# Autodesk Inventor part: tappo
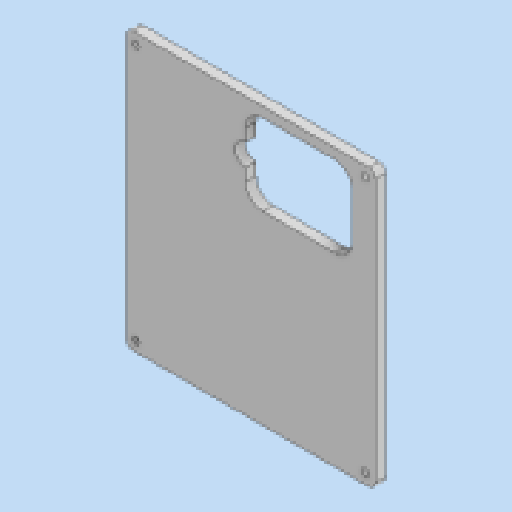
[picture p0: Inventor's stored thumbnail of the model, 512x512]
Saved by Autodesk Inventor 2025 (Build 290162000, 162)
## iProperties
Created: 2025-03
Part Number: tappo
Material: Generico
Document SubType Name: Modeling
Designer: Ryzen5700u
Density: 1 g/cm^3
Appearance: Default
Author: Ryzen5700u
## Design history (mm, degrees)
sketch "Schizzo1"
  geometry: L1 (-13.5, -12.599)-(15.5, -12.599) reference; L2 (15.5, -12.599)-(15.5, -10.099) reference; L3 (15.5, -10.099)-(-7, -10.099) reference; L4 (-7, -10.099)-(-13, -5.599) reference; L5 (-13, -5.599)-(-13, 60.901) reference; L6 (-13, 60.901)-(-7, 66.901) reference; L7 (-7, 66.901)-(50, 66.901) reference; L8 (50, 66.901)-(56, 62.401) reference; L9 (56, 62.401)-(56, -5.432) reference; L10 (56, -5.432)-(52.5, -10.099) reference; L11 (52.5, -10.099)-(52.5, -12.599) reference; L12 (52.5, -12.599)-(56.5, -12.599) reference; L13 (58.5, -10.599)-(58.5, 67.401) reference; L14 (56.5, 69.401)-(-13.5, 69.401) reference; L15 (-15.5, 67.401)-(-15.5, -10.599) reference; L16 (52.5, -12.599)-(15.5, -12.599); L17 (51.5, 47.401)-(51.5, 61.401) reference; L18 (46.5, 66.401)-(25, 66.401) reference; L19 (25, 42.401)-(46.5, 42.401) reference; L20 (20, 61.401)-(20, 47.401) reference; C1 r 1 at (-12.5, 66.401) reference; C2 r 1 at (55.5, 66.401) reference; C3 r 1 at (55.5, -9.599) reference; C4 r 1 at (-12.5, -9.599) reference; C5 r 3.23 at (20, 54.401); A1 r 2 centre (-13.5, -10.599) between (-15.5, -10.599) and (-13.5, -12.599) reference; A2 r 2 centre (56.5, -10.599) between (56.5, -12.599) and (58.5, -10.599) reference; A3 r 2 centre (56.5, 67.401) between (58.5, 67.401) and (56.5, 69.401) reference; A4 r 2 centre (-13.5, 67.401) between (-13.5, 69.401) and (-15.5, 67.401) reference; A5 r 5 centre (46.5, 61.401) between (51.5, 61.401) and (46.5, 66.401) reference; A6 r 5 centre (46.5, 47.401) between (46.5, 42.401) and (51.5, 47.401) reference; A7 r 5 centre (25, 47.401) between (20, 47.401) and (25, 42.401) reference; A8 r 5 centre (25, 61.401) between (25, 66.401) and (20, 61.401) reference; 3 further points
  constraints: 2 end point, 1 centre point, 1 horizontal, 1 midpoint
extrude "Estrusione1" new body sketch "Schizzo1" distance "d0" = 3; taper "d1" = 0 deg
sketch "Schizzo2"
  geometry: L1 (58.5, -10.599)-(58.5, 67.401) reference; L2 (56.5, 69.401)-(-13.5, 69.401) reference; L3 (-15.5, 67.401)-(-15.5, -10.599) reference; L4 (-13.5, -12.599)-(56.5, -12.599) reference; L5 (25, 66.401)-(46.5, 66.401) reference; L6 (51.5, 61.401)-(51.5, 47.401) reference; L7 (46.5, 42.401)-(25, 42.401) reference; L8 (20, 47.401)-(20, 51.171) reference; L9 (20, 57.631)-(20, 61.401) reference; L10 (50.5, 47.401)-(50.5, 61.401); L11 (46.5, 65.401)-(25, 65.401); L12 (21, 61.401)-(21, 56.395); L13 (21, 52.408)-(21, 47.401); L14 (25, 43.401)-(46.5, 43.401); C1 r 1 at (-12.5, -9.599) reference; C2 r 1 at (55.5, -9.599) reference; C3 r 1 at (55.5, 66.401) reference; C4 r 1 at (-12.5, 66.401) reference; A1 r 2 centre (56.5, -10.599) between (56.5, -12.599) and (58.5, -10.599) reference; A2 r 2 centre (56.5, 67.401) between (58.5, 67.401) and (56.5, 69.401) reference; A3 r 2 centre (-13.5, 67.401) between (-13.5, 69.401) and (-15.5, 67.401) reference; A4 r 2 centre (-13.5, -10.599) between (-15.5, -10.599) and (-13.5, -12.599) reference; A5 r 5 centre (25, 61.401) between (25, 66.401) and (20, 61.401) reference; A6 r 5 centre (46.5, 61.401) between (51.5, 61.401) and (46.5, 66.401) reference; A7 r 5 centre (46.5, 47.401) between (46.5, 42.401) and (51.5, 47.401) reference; A8 r 5 centre (25, 47.401) between (20, 47.401) and (25, 42.401) reference; A9 r 3.23 centre (20, 54.401) between (20, 57.631) and (20, 51.171) reference; A10 r 4 centre (46.5, 61.401) between (50.5, 61.401) and (46.5, 65.401); A11 r 4 centre (25, 61.401) between (25, 65.401) and (21, 61.401); A12 r 2.23 centre (20, 54.401) between (21, 56.395) and (21, 52.408); A13 r 4 centre (25, 47.401) between (21, 47.401) and (25, 43.401); A14 r 4 centre (46.5, 47.401) between (46.5, 43.401) and (50.5, 47.401); 1 further point
  constraints: 10 end point, 10 point on circle, 5 centre point, 9 other
  dimensions: "d2" = 1 distance between parallel lines of L6 L10
extrude "Estrusione2" join sketch "Schizzo2" distance "d3" = 7.5; taper "d4" = 0 deg
fillet "Raccordo1" dims "d5" = 2
fillet "Raccordo2" dims "d6" = 2
node "Solido1"
node "Riferimento1"
node "Riferimento2"
node "Riferimento3"
node "Riferimento4"
node "Riferimento5"
node "Riferimento6"
node "Riferimento7"
node "Riferimento8"
node "Riferimento9"
feature "Ѕ耀І耀Ї耀Ј耀Љ耀Њ耀Ћ耀Ќ耀"
node "Linea chiusa proiettata1"
feature "л耀м耀н耀о耀п耀р耀с耀т耀"
